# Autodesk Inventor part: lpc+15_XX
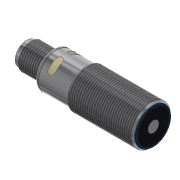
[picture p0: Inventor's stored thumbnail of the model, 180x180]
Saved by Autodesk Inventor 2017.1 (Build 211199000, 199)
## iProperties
Shininess: 20.0
Length Units: 11269
Angle Units: 11279
Time Units: 11290
Mass Units: 11283
Length Display Precision: 2
Angle Display Precision: 2
Part Number: lpc+15_XX
Material: Nichtrostender Stahl - 440C
Document SubType Name: Modellieren
Description: Ipc-25 /CXX/M18
Checked By: Alves
Created: 2005-08
Designer: Ohle
Manufacturer: Standard
Standards Organization: Custom
Appearance: Aluminium - poliert
Density: 0.0
Volumn: 0.0
Area: 0.0
PropertySet Name: Model Information
Control State: 0
Master: False
Checked Out: False
BESTELLNUMMER: Ipc-25 /CXX/M18
ME: ST
Title: Ipc Sensoren
Author: Ohle
Comments: keine Bemerkung
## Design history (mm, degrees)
sketch "Skizze10"
  geometry: L1 (-42.478, 0)-(7.522, 0); L2 (-38.478, 6.5)-(-38.478, 7.25); L3 (-45.9, 8)-(-45.9, 8); L4 (-22.728, 9)-(6.272, 9); L5 (7.512, 7.4)-(7.512, 2.5); L6 (7.512, 2.5)-(7.522, 2.5); L7 (7.522, 2.5)-(7.522, 0); L8 (7.522, 0)-(-82, 0); L9 (1.522, 8.25)-(1.522, 8.25); L10 (-23.478, 8.25)-(-22.728, 9); L11 (7.022, 8.25)-(6.272, 9); L12 (-49.978, 6)-(-38.978, 6); L13 (-36.878, 8.25)-(-23.478, 8.25); L14 (-50.478, 4.5)-(-42.478, 4.5); L15 (-42.478, 0)-(-42.478, 4.5); L16 (-36.978, 8.25)-(-37.478, 8.25); L17 (7.022, 8.25)-(7.022, 8.25); L18 (-38.978, 6)-(-38.478, 6.5); L19 (-50.478, 5.5)-(-50.478, 4.5); L20 (-50.478, 5.5)-(-49.978, 6); L21 (-36.978, 8.25)-(-36.978, 8.15); L22 (-36.978, 8.15)-(-36.878, 8.15); L23 (-36.878, 8.15)-(-36.878, 8.25); L24 (7.022, 8.25)-(7.222, 8.25); L25 (7.522, 7.95)-(7.522, 7.4); L26 (7.522, 7.4)-(7.512, 7.4); A1 r 1 centre (-37.478, 7.25) between (-37.478, 8.25) and (-38.478, 7.25); A2 r 0.3 centre (7.222, 7.95) between (7.522, 7.95) and (7.222, 8.25); 4 further points
  constraints: 52 end point, 8 point on line, 6 perpendicular, 5 parallel, 4 point on circle, 4 tangent, 2 centre point, 2 horizontal, 1 collinear
  dimensions: "d136" = 2.5 distance of L6.end L1.end; "d138" = 9 distance between parallel lines of L4 L8; "d171" = 4.5 distance between parallel lines of L14 L1; "d250" = 0.75 distance from line of L11.start L4; "d256" = 45 deg angle of L4 L10; "d257" = 8.25 distance between parallel lines of L8 L13; "d263" = 8.25 distance between parallel lines of L8 L16; "d266" = 12 distance from line of L2 L19.start; "d269" = 6 distance between parallel lines of L8 L12; "d289" = 135 deg angle of L11 L4; "d290" = 0.5 horizontal distance of L12.end L2.start; "d291" = 45 deg angle of L18 L12 (derived); "d293" = 0.5 horizontal distance of L19.start L12.start; "d294" = 45 deg angle of L20 L12 (derived); "d295" = 8 distance of L14.start L14.end; "d296" = 1.5 distance of L16.start point (-38.478, 8.25); "d297" = 0.1 distance of L21.end L22.end; "d298" = 8.15 distance between parallel lines of L22 L1; "d299" = 15 distance from line of L10.start L2; "d300" = 1 radius of A1; "d331" = 0.01 distance between parallel lines of L5 L7; "d334" = 0.5 distance of L17.end point (7.522, 8.25); "d335" = 0.3 radius of A2; "d337" = 30.5 distance of L10.start L11.start; "d338" = 0.01 distance between parallel lines of L25 L5; "d339" = 7.4 distance between parallel lines of L8 L26
revolve "Grundkörper pico+" sketch "Skizze10" stored, may be unused: angle "d168" = 90 deg
feature "Gewinde M12" dims "d174" = 10, "d175" = 0
feature "Gewinde M 18" dims "d179" = 10, "d180" = 0
workplane "Arbeitsebene1"
workplane "Arbeitsebene2"
sketch "Skizze13"
  geometry: L1 (-3.409, -3.409)-(3.61, 3.61); L2 (-3.439, 3.439)-(4.105, -4.105); L3 (-12.6, 0)-(12.6, 0) reference; C1 r 0.5 at (2.121, -2.121); C2 r 0.5 at (2.121, 2.121); C3 r 0.5 at (-2.121, 2.121); C4 r 0.5 at (-2.121, -2.121); C5 r 4.5 at (0, 0) reference; C6 r 0.5 at (0, 0); A1 r 3 centre (0, 0) between (-2.121, 2.121) and (2.121, 2.121); 2 further points
  constraints: 6 centre point, 6 point on line, 4 coincident, 4 end point, 4 equal radius, 4 point on circle, 1 horizontal alignment, 1 perpendicular
  dimensions: "d208" = 1 diameter of C3; "d209" = 6 diameter of A1
extrude "Pole" join sketch "Skizze13" distance "d212" = 7; taper "d213" = 0 deg
fillet "Rundung Pole" dims "d214" = 0.5
sketch "Skizze14"
  geometry: C1 r 0.5 at (0, -4.5); A1 r 4.5 centre (0, 0) between (4.435, -0.762) and (4.435, 0.762); A2 r 4.5 centre (0, 0) between (0, 4.5) and (0.499, 4.472) reference; A3 r 0.5 centre (0, 4.5) between (-0.499, 4.472) and (0.499, 4.472); 3 further points
  constraints: 9 point on circle, 3 centre point, 3 coincident, 1 horizontal alignment, 1 vertical alignment
  dimensions: "d215" = 9 diameter of A1; "d280" = 1 diameter of A3; "d330" = 1 diameter of C1
extrude "Verdrehsicherung" join sketch "Skizze14" distance "d217" = 7; taper "d218" = 0 deg
sketch "Skizze18"
  geometry: C1 r 7.25 at (0, 0) reference; C2 r 1 at (-8.15, 0)
  constraints: 1 centre point, 1 horizontal alignment
  dimensions: "d328" = 2 diameter of C2; "d329" = 8.15 distance of C1.centre C2.centre
extrude "Bohrung Ausrichtung" cut sketch "Skizze18" distance "d316" = 0.75; taper "d317" = 0 deg
workplane "Arbeitsebene4"
sketch "Skizze19"
  geometry: L1 (-38.478, 0)-(-30.18, 0); L2 (-34.178, -7.5)-(-34.178, -3); L3 (-31.178, -7.5)-(-31.178, -3); L4 (-31.178, 3)-(-31.178, 7.5); L5 (-34.178, 3)-(-34.178, 7.5); A1 r 1.5 centre (-32.678, 3) between (-31.178, 3) and (-34.178, 3); A2 r 1.5 centre (-32.678, -3) between (-34.178, -3) and (-31.178, -3); A3 r 1.5 centre (-32.678, 7.5) between (-31.178, 7.5) and (-34.178, 7.5); A4 r 1.5 centre (-32.678, -7.5) between (-34.178, -7.5) and (-31.178, -7.5); 4 further points; 1 other entity
  constraints: 10 end point, 8 point on circle, 8 tangent, 4 centre point, 3 equal radius, 2 vertical alignment, 1 horizontal, 2 other
  dimensions: "d319" = 3 diameter of A2; "d320" = 6 distance of A2.centre A1.centre; "d321" = 4.5 distance of A1.centre A3.centre; "d322" = 4.5 distance of A4.centre A2.centre; "d323" = 3 distance from line of A2.centre L1; "d324" = 5.8 dimension on A1.centre; "d325" = 5.8 dimension on A2.centre
feature "Prägen LED-Fenster" sketch "Skizze19" dims "d326" = 0.01, "d327" = 0
sketch "Skizze20"
  geometry: C1 r 5.5 at (0, 0) reference; C2 r 4.5 at (0, 0) reference; C3 r 4.15 at (0, 0); C4 r 5.25 at (0, 0); 1 further point
  constraints: 2 centre point
  dimensions: "d340" = 8.3 diameter of C3; "d341" = 10.5 diameter of C4
extrude "Extrusion5" join sketch "Skizze20" distance "d342" = 0.2; taper "d343" = 0 deg
sketch "Skizze21"
  geometry: C1 r 4.15 at (0, 0) reference; C2 r 5.25 at (0, 0) reference; C3 r 6 at (0, 0); 1 further point
  constraints: 1 centre point
  dimensions: "d344" = 12 diameter of C3
extrude "Extrusion6" cut sketch "Skizze21" distance "d345" = 1.8; taper "d346" = 0 deg
chamfer "Fase2" distance "d347" = 0.75; stored, may be unused: second distance "d348" = 2, angle "d349" = 30 deg
node "Volumenkörper1"
node "Volumenkörper"
node "Flächenkörper"
node "Projizierte Kontur2"
node "Projizierte Kontur3"
other parameters: "d10" = 14, "d73" = -35, "d130" = 0.2, "d207" = -95.5, "d318" = 8.25
